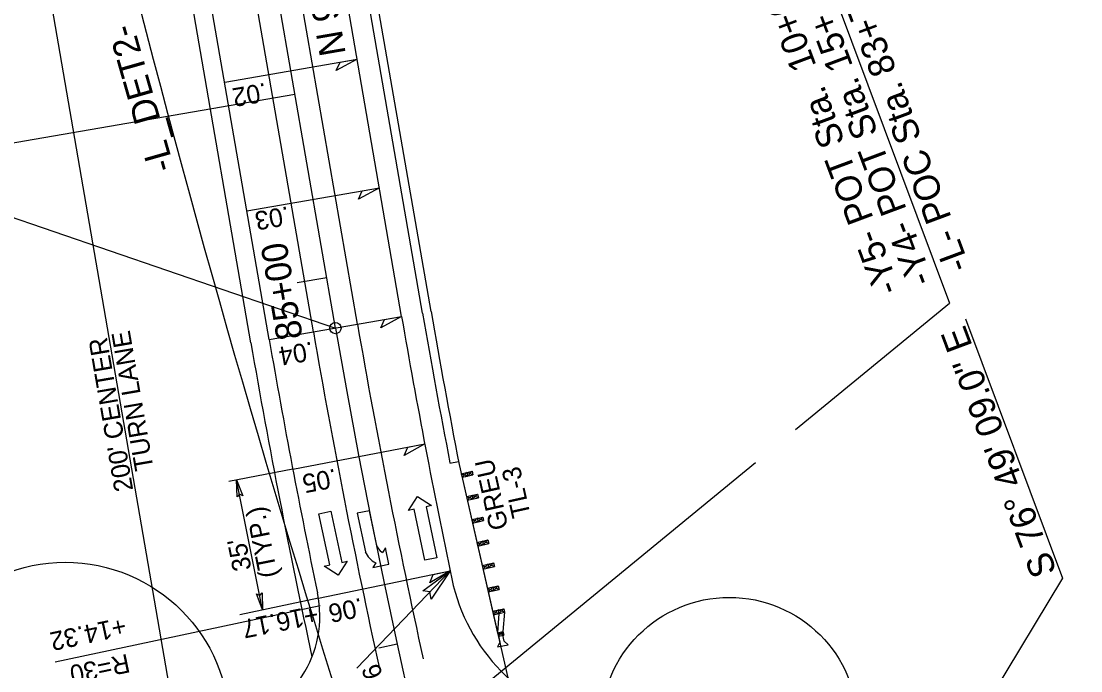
# Model space of a CAD drawing. Extents: x 472216 to 481979, y 489069 to 507339.
# Drawn here: x 478350.7 to 478634.5, y 495030.5 to 495204.6 of the extents above; entities that cross this region are included whole.
import ezdxf

# ---------------------------------------------------------------- set-up
doc = ezdxf.new("R2010")
doc.units = 0
for name, color, linetype in [('Old_Level_12', 7, 'Continuous'), ('Prop Drainage Structure Drop Inlet Grate 2 Narrow Slots and Sag Grates 840 24 CELL', 7, 'Continuous'), ('Prop Drainage Structure Drop Inlet Grate 2 Wide Slots and Sag Grates 840 22 Label', 7, 'Continuous'), ('Prop Drainage Structure Outlet Berm Ditch 850 10 CELL', 7, 'Continuous'), ('Prop Drainage Structure Pipe CSP 15in', 7, 'Continuous'), ('Prop Drainage Structure Pipe Plug CELL', 7, 'Continuous'), ('Prop Drainage Structure Pipe RCP 15in Class III Label', 7, 'Continuous'), ('Prop Drainage Structure Pipe RCP 24in Class III Label', 7, 'Continuous'), ('Prop Drainage Structure Pipe Side Drain 15in Label', 7, 'Continuous'), ('Prop Drainage Structure Tops and Inverts LABEL', 7, 'Continuous'), ('Prop Earthen Structure False Sump CELL', 7, 'Continuous'), ('Prop Erosion Embankment Toe Protection CELL', 7, 'Continuous'), ('Sheet Block Revision CELL', 7, 'Continuous'), ('Sheet Block Title CELL', 7, 'Continuous'), ('Sheet North Arrow Point CELL', 7, 'Continuous'), ('Sheet PE Seal Cell', 7, 'Continuous'), ('Sheet Plan And Profile CELL', 7, 'Continuous'), ('Sheet Plot Border Outside CELL', 7, 'Continuous'), ('Sheet Profile Grid Major CELL', 7, 'Continuous'), ('Sheet Profile Grid Minor CELL', 7, 'Continuous')]:
    doc.layers.add(name, color=color, linetype=linetype)

msp = doc.modelspace()

# ---------------------------------------------------------------- linework, layer by layer
at = {"layer": 'Old_Level_12'}
for p, q in [((478553.14, 495252.8), (478599.36, 495129)), ((478291.59, 495171.56), (478434.84, 495122.34)), ((478558.07, 495095.12), (478599.36, 495129)), ((478603.69, 495124.81), (478629.62, 495055.35)), ((478457.03, 495012.18), (478547.36, 495086.32)), ((478629.62, 495055.35), (478585.55, 494982.08))]:
    msp.add_line(p, q, dxfattribs=at)
msp.add_circle((478434.84, 495122.35), 1.5, dxfattribs=at)
msp.add_circle((478434.84, 495122.35), 1.5, dxfattribs=at)
at = {"layer": 'Prop Drainage Structure Drop Inlet Grate 2 Narrow Slots and Sag Grates 840 24 CELL'}
for p, q in [((478423.42, 495084.54), (478406.24, 495081.27)), ((478415.33, 495046.79), (478408.37, 495081.68)), ((478430.33, 495049.92), (478409.25, 495045.53))]:
    msp.add_line(p, q, dxfattribs=at)
for points in [[(478440.64, 495194.4), (478435.07, 495191.4), (478436.09, 495193.61)], [(478446.61, 495159.91), (478441.04, 495156.91), (478442.05, 495159.12)], [(478452.58, 495125.42), (478447.01, 495122.43), (478448.02, 495124.63)], [(478458.78, 495091.29), (478453.26, 495088.2), (478454.24, 495090.42)], [(478408.49, 495077.11), (478408.37, 495081.67), (478410.04, 495077.39), (478409.14, 495077.8)], [(478465.57, 495057.27), (478460.11, 495054.08), (478461.04, 495056.32)], [(478415.21, 495051.36), (478415.33, 495046.79), (478413.66, 495051.08), (478414.55, 495050.67)]]:
    msp.add_lwpolyline(points, close=True, dxfattribs=at)
at = {"layer": 'Prop Drainage Structure Drop Inlet Grate 2 Wide Slots and Sag Grates 840 22 Label'}
for p, q in [((478405.17, 495188.26), (478440.64, 495194.4)), ((478411.14, 495153.77), (478446.61, 495159.91)), ((478417.1, 495119.28), (478452.58, 495125.42)), ((478423.42, 495084.55), (478458.78, 495091.29)), ((478430.33, 495049.92), (478465.57, 495057.27))]:
    msp.add_line(p, q, dxfattribs=at)
at = {"layer": 'Prop Drainage Structure Outlet Berm Ditch 850 10 CELL'}
msp.add_lwpolyline([(478458.22, 495051.89), (478465.56, 495057.32), (478460.46, 495049.68), (478460.1, 495051.62)], close=True, dxfattribs=at)
at = {"layer": 'Prop Drainage Structure Pipe Plug CELL'}
for p, q in [((478467.99, 495085.8), (478478.36, 495040.21)), ((478468.55, 495083.32), (478471.48, 495083.99)), ((478470.23, 495082.68), (478471.48, 495083.99)), ((478471.48, 495083.99), (478471.7, 495083.01)), ((478468.55, 495083.32), (478468.77, 495082.35)), ((478470.23, 495082.68), (478468.55, 495083.32)), ((478470.01, 495083.65), (478468.77, 495082.35)), ((478468.77, 495082.35), (478471.7, 495083.01)), ((478468.77, 495082.35), (478470.23, 495082.68)), ((478470.01, 495083.65), (478470.23, 495082.68)), ((478471.7, 495083.01), (478470.01, 495083.65)), ((478469.95, 495077.18), (478472.92, 495077.85)), ((478469.95, 495077.18), (478471.66, 495076.54)), ((478471.44, 495077.51), (478470.17, 495076.2)), ((478470.17, 495076.2), (478473.15, 495076.88)), ((478471.44, 495077.51), (478471.66, 495076.54)), ((478473.15, 495076.88), (478471.44, 495077.51)), ((478471.66, 495076.54), (478472.92, 495077.85)), ((478472.92, 495077.85), (478473.15, 495076.88)), ((478471.35, 495071.03), (478474.32, 495071.71)), ((478471.35, 495071.03), (478473.05, 495070.39)), ((478472.83, 495071.37), (478471.57, 495070.06)), ((478471.57, 495070.06), (478474.54, 495070.73)), ((478472.83, 495071.37), (478473.05, 495070.39)), ((478474.54, 495070.73), (478472.83, 495071.37)), ((478473.05, 495070.39), (478474.32, 495071.71)), ((478474.32, 495071.71), (478474.54, 495070.73)), ((478472.74, 495064.89), (478475.7, 495065.56)), ((478472.74, 495064.89), (478472.96, 495063.91)), ((478472.74, 495064.89), (478474.45, 495064.25)), ((478474.22, 495065.22), (478472.96, 495063.91)), ((478472.96, 495063.91), (478475.92, 495064.59)), ((478474.22, 495065.22), (478474.45, 495064.25)), ((478475.92, 495064.59), (478474.22, 495065.22)), ((478474.45, 495064.25), (478475.7, 495065.56)), ((478475.7, 495065.56), (478475.92, 495064.59)), ((478474.14, 495058.74), (478477.2, 495059.44)), ((478474.14, 495058.74), (478475.89, 495058.12)), ((478475.67, 495059.09), (478474.36, 495057.77)), ((478474.36, 495057.77), (478477.42, 495058.46)), ((478475.67, 495059.09), (478475.89, 495058.12)), ((478477.42, 495058.46), (478475.67, 495059.09)), ((478475.89, 495058.12), (478477.2, 495059.44)), ((478477.2, 495059.44), (478477.42, 495058.46)), ((478475.54, 495052.6), (478478.46, 495053.26)), ((478475.54, 495052.6), (478477.22, 495051.96)), ((478477, 495052.93), (478475.76, 495051.62)), ((478477, 495052.93), (478477.22, 495051.96)), ((478478.69, 495052.29), (478477, 495052.93)), ((478477.22, 495051.96), (478478.46, 495053.26)), ((478478.46, 495053.26), (478478.69, 495052.29)), ((478475.76, 495051.62), (478478.69, 495052.29)), ((478476.94, 495046.45), (478479.92, 495047.13)), ((478478.65, 495045.82), (478479.92, 495047.13)), ((478479.92, 495047.13), (478480.15, 495046.16)), ((478476.94, 495046.45), (478478.65, 495045.82)), ((478478.43, 495046.79), (478477.16, 495045.48)), ((478477.16, 495045.48), (478480.15, 495046.16)), ((478478.65, 495045.82), (478478.24, 495040.7)), ((478478.43, 495046.79), (478478.65, 495045.82)), ((478480.15, 495046.16), (478478.43, 495046.79)), ((478480.15, 495046.16), (478479.71, 495041.03)), ((478478.24, 495040.7), (478479.71, 495041.03)), ((478479.93, 495040.06), (478478.24, 495040.7)), ((478479.03, 495040.32), (478478.44, 495040.2)), ((478478.44, 495040.2), (478478.85, 495038.19)), ((478478.47, 495039.73), (478479.71, 495041.03)), ((478478.47, 495039.73), (478479.93, 495040.06)), ((478479.63, 495040.45), (478479.03, 495040.32)), ((478480.05, 495038.45), (478479.63, 495040.45)), ((478479.71, 495041.03), (478479.82, 495040.55)), ((478479.71, 495041.03), (478479.93, 495040.06)), ((478481.13, 495037.47), (478480.05, 495038.45)), ((478478.85, 495038.19), (478478.25, 495036.87)), ((478478.25, 495036.87), (478481.13, 495037.47))]:
    msp.add_line(p, q, dxfattribs=at)
at = {"layer": 'Prop Drainage Structure Pipe RCP 15in Class III Label'}
for p, q in [((478440.75, 495123.37), (478402.72, 495343.19)), ((478428.93, 495121.32), (478390.9, 495341.15))]:
    msp.add_line(p, q, dxfattribs=at)
for radius in [2056, 2044]:
    msp.add_arc((480454.83, 495471.85), radius, 189.81618, 192.37847, dxfattribs=at)
at = {"layer": 'Prop Drainage Structure Pipe RCP 24in Class III Label'}
for p, q in [((478452.58, 495125.42), (478414.54, 495345.24)), ((478417.1, 495119.28), (478379.07, 495339.1)), ((478465.53, 495086.18), (478467.83, 495086.63))]:
    msp.add_line(p, q, dxfattribs=at)
for centre, radius, start, end in [((480454.83, 495471.85), 2032, 189.81618, 191.83436), ((480454.83, 495471.85), 2068, 189.81618, 191.73204), ((478514.96, 495065.37), 50, 191.8344, 256.8192), ((478400.66, 495045.25), 30, 283.1168, 11.732)]:
    msp.add_arc(centre, radius, start, end, dxfattribs=at)
at = {"layer": 'Prop Drainage Structure Pipe Side Drain 15in Label'}
for p, q in [((478454.45, 495073.49), (478456.84, 495077.21)), ((478456.84, 495077.21), (478460.62, 495074.79)), ((478430.42, 495072.55), (478433.65, 495073.23)), ((478433.31, 495058.85), (478430.42, 495072.55)), ((478433.65, 495073.23), (478436.54, 495059.53)), ((478443.93, 495073.39), (478440.7, 495072.71)), ((478440.7, 495072.71), (478442.87, 495062.39)), ((478445.81, 495064.44), (478443.93, 495073.39)), ((478455.92, 495073.8), (478454.45, 495073.49)), ((478458.8, 495060.1), (478455.92, 495073.8)), ((478460.62, 495074.79), (478459.15, 495074.48)), ((478459.15, 495074.48), (478462.03, 495060.78)), ((478448.26, 495063.47), (478447.45, 495062.23)), ((478449.14, 495059.06), (478448.26, 495063.47)), ((478431.84, 495058.54), (478433.31, 495058.85)), ((478435.62, 495056.12), (478431.84, 495058.54)), ((478438, 495059.84), (478435.62, 495056.12)), ((478436.54, 495059.53), (478438, 495059.84)), ((478445.63, 495059.45), (478444.82, 495058.2)), ((478444.82, 495058.2), (478449.14, 495059.06)), ((478462.03, 495060.78), (478458.8, 495060.1))]:
    msp.add_line(p, q, dxfattribs=at)
for centre, radius, start, end in [((478449, 495065.1), 3.27, 191.8857, 241.5439), ((478447.77, 495064.23), 5.25, 200.5618, 245.8735)]:
    msp.add_arc(centre, radius, start, end, dxfattribs=at)
at = {"layer": 'Prop Drainage Structure Tops and Inverts LABEL'}
msp.add_line((478460.46, 495126.78), (478422.43, 495346.6), dxfattribs=at)
msp.add_arc((480454.83, 495471.85), 2024, 189.81618, 190.99568, dxfattribs=at)
at = {"layer": 'Prop Earthen Structure False Sump CELL'}
msp.add_line((478458.16, 495126.38), (478420.13, 495346.2), dxfattribs=at)
msp.add_arc((480454.83, 495471.85), 2026.33, 189.81618, 190.97176, dxfattribs=at)
at = {"layer": 'Prop Erosion Embankment Toe Protection CELL'}
for p, q in [((478460.46, 495126.78), (478422.43, 495346.6)), ((478412.18, 495118.43), (478374.14, 495338.25)), ((478467.99, 495085.8), (478481.04, 495028.64))]:
    msp.add_line(p, q, dxfattribs=at)
for radius, end in [(2024, 190.99568), (2073, 192.18764)]:
    msp.add_arc((480454.83, 495471.85), radius, 189.81618, end, dxfattribs=at)
at = {"layer": 'Sheet Block Revision CELL'}
for p, q in [((478391.62, 495019.03), (478331.63, 495366.81)), ((478465.56, 495057.32), (478440.58, 495031.23)), ((478430.75, 495047.92), (478359.71, 495032.77))]:
    msp.add_line(p, q, dxfattribs=at)
at = {"layer": 'Sheet Block Title CELL'}
msp.add_line((478226.92, 495150.97), (478423.99, 495185.07), dxfattribs=at)
at = {"layer": 'Sheet North Arrow Point CELL'}
msp.add_line((478434.84, 495122.35), (478396.81, 495342.17), dxfattribs=at)
for centre, radius, start, end in [((481983.35, 496141.85), 3720, 188.99254, 203.7418), ((480454.83, 495471.85), 2050, 189.81618, 250.32977)]:
    msp.add_arc(centre, radius, start, end, dxfattribs=at)
at = {"layer": 'Sheet PE Seal Cell'}
msp.add_line((478451.35, 495037.6), (478446.46, 495036.54), dxfattribs=at)
at = {"layer": 'Sheet Plot Border Outside CELL'}
for centre, radius in [((478362.44, 495015.53), 44.04), ((478540.38, 495015.78), 34.39)]:
    msp.add_circle(centre, radius, dxfattribs=at)
at = {"layer": 'Sheet Profile Grid Minor CELL'}
msp.add_line((478432.51, 495135.8), (478424.63, 495134.44), dxfattribs=at)

# ---------------------------------------------------------------- texts
at = {"layer": 'Old_Level_12'}
for s, p in [('-Y5- POT Sta.  10+00.00=', (478586.17, 495132.74)), ('-Y4- POT Sta. 15+46.75=', (478595.06, 495135.12)), ('-L- POC Sta. 83+73.95', (478604.9, 495138.79))]:
    msp.add_text(s, height=7, rotation=110.469, dxfattribs=at).set_placement(p)
at = {"layer": 'Prop Drainage Structure Drop Inlet Grate 2 Narrow Slots and Sag Grates 840 24 CELL'}
for s, rotation, p in [('.02', 189.8162, (478416.06, 495188.12)), ('.03', 189.8162, (478422.11, 495155.02)), ('.04', 189.8163, (478428.53, 495118.75)), ('.05', 190.7945, (478434.77, 495084.7)), ('(TYP.)', 101.2836, (478419.43, 495055.92)), ("35'", 101.2836, (478412.38, 495057.75)), ('.06', 191.7727, (478441.7, 495050.06)), ('+16.17', 191.2836, (478429.73, 495048.07))]:
    msp.add_text(s, height=5, rotation=rotation, dxfattribs=at).set_placement(p)
at = {"layer": 'Prop Drainage Structure Pipe CSP 15in'}
for s, rotation, p in [('TURN LANE ', 99.7865, (478386.15, 495084.59)), ("200' CENTER ", 99.7865, (478380.68, 495078.97)), ('+14.32', 192.0367, (478378.2, 495044.96)), ("R=30'", 191.718, (478379.14, 495035.07)), ('+16.76', 110.469, (478453.58, 495013.47))]:
    msp.add_text(s, height=5, rotation=rotation, dxfattribs=at).set_placement(p)
at = {"layer": 'Prop Drainage Structure Pipe Plug CELL'}
for s, p in [('GREU', (478481.2, 495068.83)), ('TL-3', (478487.18, 495072.14))]:
    msp.add_text(s, height=5, rotation=102.5263, dxfattribs=at).set_placement(p)
at = {"layer": 'Sheet Plan And Profile CELL'}
for s, rotation, p in [('N 9%%d 48\' 58.3" W', 99.8162, (478437.64, 495195.92)), ('S 76%%d 49\' 09.0" E', 110.469, (478628.18, 495057.1))]:
    msp.add_text(s, height=7, rotation=rotation, dxfattribs=at).set_placement(p)
at = {"layer": 'Sheet Profile Grid Major CELL'}
for s, rotation, p in [('-L_DET2-', 105.8736, (478391.73, 495165.23)), ('85+00', 99.8162, (478426.14, 495119.82))]:
    msp.add_text(s, height=7, rotation=rotation, dxfattribs=at).set_placement(p)

doc.saveas('drawing.dxf')
